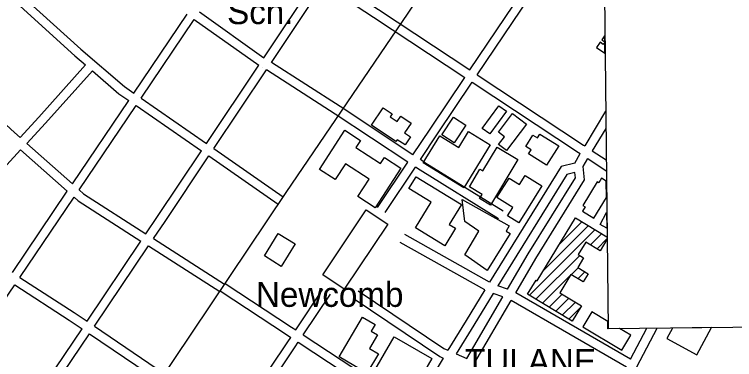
# Model space of a CAD drawing. Extents: x 3651524 to 3689615, y 505651 to 531377.
# Drawn here: x 3663276 to 3665685, y 525966 to 527122 of the extents above; entities that cross this region are included whole.
import ezdxf

# ---------------------------------------------------------------- set-up
doc = ezdxf.new("R2010")
doc.units = 0
for name, color, linetype in [('V-ANNO-SYMB', 7, 'Continuous'), ('V-BLDG-IDEN', 7, 'Continuous'), ('V-BLDG-OTLN', 7, 'Continuous'), ('V-ROAD-CNTR', 7, 'Continuous')]:
    doc.layers.add(name, color=color, linetype=linetype)

msp = doc.modelspace()

# ---------------------------------------------------------------- linework, layer by layer
at = {"layer": 'V-ANNO-SYMB'}
msp.add_lwpolyline([(3665232.757, 528916.237), (3677598.144, 529049.331), (3677628.792, 526201.948), (3665263.405, 526068.854)], close=True, dxfattribs=at)
at = {"layer": 'V-BLDG-OTLN'}
for p, q in [((3665250.976, 527030.456), (3665250.751, 527050.501)), ((3665251.414, 526991.548), (3665250.998, 527028.556)), ((3665256.846, 526508.801), (3665256.228, 526563.731)), ((3665257.415, 526458.191), (3665258.008, 526405.55)), ((3665044.82, 526262.455), (3665196.718, 526414.353)), ((3665098.726, 526351.716), (3665174.674, 526427.665)), ((3664998.791, 526181.072), (3665218.761, 526401.041)), ((3665203.078, 526350.003), (3665240.803, 526387.729)), ((3665225.121, 526336.691), (3665258.408, 526369.978)), ((3665020.834, 526167.76), (3665167.244, 526314.169)), ((3665138.419, 526249.989), (3665161.859, 526273.428)), ((3665042.878, 526154.448), (3665136.609, 526248.179)), ((3665160.463, 526236.678), (3665183.902, 526260.116)), ((3665064.921, 526141.136), (3665108.605, 526184.82)), ((3665086.964, 526127.824), (3665130.649, 526171.508)), ((3665109.008, 526114.512), (3665152.692, 526158.196)), ((3665131.051, 526101.2), (3665168.722, 526138.871)), ((3665261.793, 526069.133), (3665261.524, 526093.046)), ((3665300.623, 526069.551), (3665261.793, 526069.133)), ((3665608.238, 526072.862), (3665477.468, 526071.454))]:
    msp.add_line(p, q, dxfattribs=at)
for points in [[(3665250.751, 527050.501), (3665241.407, 527037.156), (3665250.976, 527030.456)], [(3665250.998, 527028.556), (3665245.973, 527021.38), (3665235.521, 527028.698), (3665223.296, 527011.237), (3665251.414, 526991.548)], [(3665256.228, 526563.731), (3665240.56, 526573.273), (3665230.852, 526557.332), (3665225.237, 526560.752), (3665177.327, 526482.079), (3665185.508, 526477.097), (3665176.811, 526462.815), (3665214.769, 526439.701), (3665256.846, 526508.801)], [(3665258.008, 526405.55), (3665235.162, 526418.292), (3665257.415, 526458.191)], [(3665258.428, 526368.207), (3665235.58, 526330.374), (3665187.58, 526359.362), (3665162.147, 526317.247), (3665180.119, 526306.394), (3665160.651, 526274.157), (3665195.232, 526253.274), (3665178.596, 526225.727), (3665137.894, 526250.306), (3665101.088, 526189.36), (3665172.99, 526145.938), (3665141.985, 526094.597), (3664992.77, 526184.708), (3665021.183, 526231.757), (3665024.918, 526229.501), (3665152.631, 526440.977)], [(3665152.631, 526440.977), (3665258.327, 526377.147)], [(3665261.524, 526093.046), (3665207.719, 526125.378), (3665177.943, 526075.827), (3665308.095, 525997.617)], [(3665308.095, 525997.617), (3665337.871, 526047.168), (3665300.623, 526069.551)], [(3665458.452, 526036.593), (3665558.642, 525981.941), (3665608.238, 526072.862)], [(3665477.468, 526071.454), (3665458.452, 526036.593)]]:
    msp.add_lwpolyline(points, dxfattribs=at)
for points in [[(3664921.819, 526797.765), (3664867.053, 526721.521), (3664841.386, 526739.957), (3664896.154, 526816.201)], [(3664552.572, 526695.964), (3664470.777, 526750.421), (3664509.495, 526808.575), (3664539.738, 526788.44), (3664533.042, 526778.382), (3664556.585, 526762.708), (3664568.742, 526780.968), (3664603.266, 526757.983), (3664581.169, 526724.794), (3664601.368, 526711.346), (3664583.527, 526684.549), (3664556.814, 526702.335)], [(3664786.385, 526750.712), (3664747.372, 526691.487), (3664706.105, 526718.671), (3664745.117, 526777.896)], [(3664989.093, 526754.19), (3664922.473, 526665.875), (3664896.002, 526685.843), (3664915.902, 526712.224), (3664895.329, 526727.743), (3664942.049, 526789.677)], [(3664296.394, 526602.95), (3664381.249, 526733.751), (3664433.462, 526699.879), (3664418.13, 526676.246), (3664500.712, 526622.671), (3664513.804, 526642.852), (3664568.791, 526607.18), (3664482.553, 526474.248), (3664424.853, 526511.68), (3664463.043, 526570.549), (3664384.125, 526621.745), (3664349.558, 526568.461)], [(3664779.118, 526541.005), (3664643.679, 526624.21), (3664699.366, 526714.857), (3664762.713, 526675.941), (3664795.507, 526729.323), (3664867.6, 526685.034)], [(3665056.571, 526616.828), (3664996.004, 526654.932), (3665004.346, 526668.192), (3664986.947, 526679.138), (3665010.909, 526717.227), (3665025.652, 526707.952), (3665033.912, 526721.081), (3665097.136, 526681.304)], [(3664959.779, 526635.662), (3664868.621, 526483.079), (3664832.095, 526504.901), (3664840.547, 526519.048), (3664798.267, 526544.308), (3664833.639, 526603.514), (3664843.387, 526597.69), (3664890.723, 526676.92)], [(3664716.173, 526346.571), (3664617.653, 526406.501), (3664670.3, 526493.049), (3664595.681, 526538.439), (3664619.786, 526578.066), (3664771.629, 526485.7), (3664730.725, 526418.456), (3664752.019, 526405.503)], [(3665040.357, 526548.016), (3664963.18, 526424.321), (3664926.03, 526447.5), (3664943.198, 526475.016), (3664890.162, 526508.107), (3664930.966, 526573.505), (3664965.44, 526551.995), (3664984.646, 526582.777)], [(3664774.208, 526501.942), (3664931.21, 526413.636), (3664921.607, 526396.123), (3664934.572, 526388.216), (3664857.132, 526264.229), (3664782.983, 526316.33), (3664830.026, 526396.321), (3664782.448, 526427.784)], [(3664307.972, 526249.559), (3664453.126, 526467.212), (3664524.937, 526419.321), (3664379.783, 526201.669)], [(3664214.829, 526352.932), (3664168.34, 526277.982), (3664112.331, 526312.723), (3664158.821, 526387.673)], [(3664362.753, 525975.115), (3664441.117, 526107.503), (3664482.439, 526083.043), (3664469.611, 526061.371), (3664491.212, 526048.585), (3664464.15, 526002.865), (3664493.759, 525985.339), (3664455.286, 525920.343)], [(3664469.675, 525909.251), (3664546.359, 526041.824), (3664672.43, 525968.901), (3664595.746, 525836.328)]]:
    msp.add_lwpolyline(points, close=True, dxfattribs=at)
at = {"layer": 'V-ROAD-CNTR'}
for points in [[(3662939.923, 524671.627), (3663556.362, 525585.991), (3664184.93, 526525.227), (3664593.526, 527125.754), (3664954.368, 527669.074), (3665094.157, 527888.096), (3665238.971, 528097.362)], [(3664799.641, 526936.01), (3665183.949, 527507.553)], [(3664824.666, 526919.463), (3665209.03, 527491.089)], [(3664110.027, 526976.811), (3664285.557, 527239.74)], [(3664327.253, 527248.167), (3664494.382, 527137.864), (3664799.642, 526936.011)], [(3664135.623, 526961.12), (3664310.596, 527223.216)], [(3664310.596, 527223.217), (3664477.846, 527112.832), (3664782.901, 526911.115)], [(3663315.72, 527172.275), (3663498.298, 527005.672), (3663644.284, 526880.049), (3663675.169, 526858.611)], [(3663295.545, 527150.072), (3663478.4, 526983.218), (3663514.057, 526952.533)], [(3663894.771, 527130.265), (3664110.027, 526976.811)], [(3663675.169, 526858.61), (3663853.544, 527122.812)], [(3663699.815, 526841.501), (3663877.98, 527105.392)], [(3663877.979, 527105.393), (3664093.363, 526951.849)], [(3664609.091, 526651.974), (3664365.394, 526813.448), (3664135.624, 526961.121)], [(3663294.845, 526709.83), (3663357.636, 526778.002), (3663514.057, 526952.533)], [(3663918.402, 526689.773), (3664093.363, 526951.849)], [(3663943.05, 526672.664), (3664118.964, 526936.166)], [(3664104.998, 526945.143), (3664104.998, 526945.142)], [(3664592.438, 526627.021), (3664348.998, 526788.324), (3664118.965, 526936.166)], [(3663317.308, 526689.937), (3663379.84, 526757.828), (3663536.802, 526932.961)], [(3663536.802, 526932.962), (3663625.898, 526856.293), (3663658.381, 526833.745)], [(3664609.09, 526651.974), (3664666.542, 526738.062), (3664782.901, 526911.114)], [(3664824.666, 526919.464), (3665180.087, 526684.445), (3665184.219, 526681.695)], [(3663076.863, 526909.412), (3663276.23, 526726.317), (3663294.845, 526709.831)], [(3664634.099, 526635.404), (3664691.466, 526721.367), (3664807.926, 526894.567)], [(3664807.925, 526894.568), (3665163.503, 526659.445), (3665169.09, 526655.728)], [(3663699.815, 526841.503), (3663918.402, 526689.775)], [(3663469.996, 526554.72), (3663658.381, 526833.744)], [(3663492.65, 526534.659), (3663683.027, 526816.636)], [(3663683.027, 526816.637), (3663901.742, 526664.82)], [(3665253.599, 526797.347), (3665184.219, 526681.695)], [(3665254.243, 526740.103), (3665209.223, 526665.057)], [(3663317.308, 526689.939), (3663469.997, 526554.721)], [(3663943.05, 526672.666), (3664175.59, 526511.251)], [(3663076.353, 526428.325), (3663296.981, 526667.867)], [(3663296.98, 526667.868), (3663453.065, 526529.642)], [(3663716.272, 526387.41), (3663755.155, 526445.244), (3663901.742, 526664.819)], [(3663741.521, 526371.197), (3663780.079, 526428.546), (3663926.391, 526647.709)], [(3663926.39, 526647.711), (3664158.484, 526486.607)], [(3665150.729, 526623.527), (3665169.09, 526655.727)], [(3665209.222, 526665.058), (3665255.434, 526634.307)], [(3664491.089, 526475.154), (3664592.437, 526627.02)], [(3664911.514, 526462.419), (3664649.36, 526625.291), (3664634.099, 526635.404)], [(3665150.729, 526623.527), (3665104.778, 526611.948), (3664865.935, 526224.816)], [(3664953.145, 526189.248), (3665020.661, 526304.674), (3665183.636, 526567.689), (3665179.165, 526612.833), (3665194.125, 526639.067)], [(3665194.125, 526639.069), (3665255.842, 526598)], [(3664516.043, 526458.502), (3664617.446, 526610.45)], [(3664895.682, 526436.937), (3664633.156, 526600.041), (3664617.446, 526610.45)], [(3665151.016, 526592.662), (3665123.916, 526585.832), (3664893.827, 526212.888)], [(3664925.829, 526201.967), (3664994.959, 526320.15), (3665152.78, 526574.849), (3665151.016, 526592.662)], [(3663269.173, 526257.269), (3663453.065, 526529.641)], [(3663492.65, 526534.66), (3663507.7, 526521.331), (3663716.272, 526387.411)], [(3663294.36, 526240.961), (3663475.718, 526509.581)], [(3663475.718, 526509.581), (3663489.544, 526497.337), (3663699.53, 526362.509)], [(3664865.935, 526224.816), (3664581.838, 526384.362)], [(3663519.065, 526094.096), (3663699.53, 526362.509)], [(3663741.521, 526371.198), (3663979.322, 526218.511)], [(3664850.172, 526199.261), (3664567.148, 526358.204)], [(3663543.877, 526077.233), (3663724.78, 526346.296)], [(3663724.779, 526346.297), (3663963.114, 526193.267)], [(3663294.36, 526240.963), (3663476.195, 526123.231), (3663519.064, 526094.097)], [(3663108.006, 525947.838), (3663239.616, 526159.878), (3663277.57, 526216.094)], [(3663277.57, 526216.096), (3663459.609, 526098.231), (3663502.326, 526069.2)], [(3663981.232, 526221.025), (3664203.082, 526074.6), (3664217.447, 526065.112)], [(3664925.829, 526201.967), (3664893.827, 526212.888)], [(3663964.706, 526195.987), (3664186.552, 526049.564), (3664200.794, 526040.158)], [(3664217.447, 526065.111), (3664308.174, 526201.064)], [(3664426.068, 526196.015), (3664713.206, 526002.412), (3664726.346, 525996.75)], [(3664850.171, 526199.263), (3664786.996, 526096.863), (3664726.346, 525996.75)], [(3665337.608, 525966.878), (3664953.145, 526189.248)], [(3664242.479, 526048.578), (3664333.128, 526184.412)], [(3664409.296, 526171.141), (3664698.76, 525975.97), (3664710.652, 525970.845)], [(3664877.672, 526186.701), (3664812.592, 526081.215), (3664754.16, 525984.764)], [(3664789.799, 525969.408), (3664910.373, 526175.544)], [(3664910.373, 526175.544), (3664877.672, 526186.701)], [(3664816.386, 525955.444), (3664937.997, 526163.352)], [(3665323.671, 525940.281), (3664937.997, 526163.352)], [(3663324.139, 525804.175), (3663502.326, 526069.2)], [(3663543.877, 526077.235), (3663778.525, 525917.767)], [(3664949.571, 525161.67), (3665425.981, 526070.9)], [(3665337.608, 525966.878), (3665391.92, 526070.534)], [(3663349.183, 525787.656), (3663527.138, 526052.337)], [(3663527.138, 526052.338), (3663761.663, 525892.955)], [(3664242.479, 526048.579), (3664496.517, 525880.795), (3664615.196, 525813.284)], [(3664015.801, 525763.685), (3664190.456, 526024.665), (3664200.794, 526040.158)], [(3664040.963, 525747.344), (3664215.398, 526007.997), (3664225.827, 526023.624)], [(3664225.827, 526023.625), (3664480.817, 525855.213), (3664599.645, 525787.616)], [(3664754.16, 525984.764), (3664789.799, 525969.408)], [(3664710.652, 525970.845), (3664615.196, 525813.284)]]:
    msp.add_lwpolyline(points, dxfattribs=at)

# ---------------------------------------------------------------- texts
at = {"layer": 'V-BLDG-IDEN'}
for s, p in [('Sch.', (3663987.711, 527089.305)), ('Newcomb', (3664084.195, 526142.295)), ('TULANE', (3664783.681, 525918.437))]:
    msp.add_text(s, height=82.9998, dxfattribs=at).set_placement(p)

doc.saveas('drawing.dxf')
